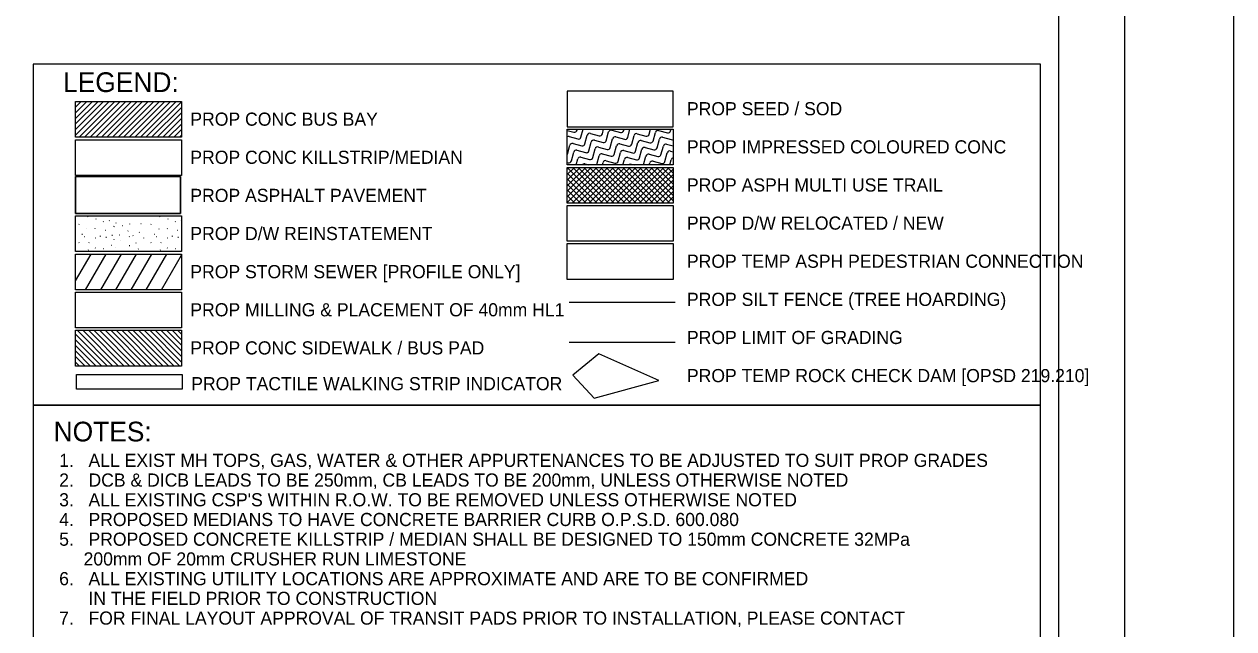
# Model space of a CAD drawing. Extents: x 595568 to 603709, y 4837996 to 4846716.
# Drawn here: x 603285 to 603377, y 4846491.1 to 4846537.1 of the extents above; entities that cross this region are included whole.
import ezdxf

# ---------------------------------------------------------------- set-up
doc = ezdxf.new("R2010")
doc.units = 0
for name, color, linetype in [('-PRINT FULLSIZE', 7, 'Continuous'), ('-PRINT HALFSIZE', 7, 'Continuous'), ('ENG_BORDER', 7, 'Continuous'), ('ENG_FENCE_SILT', 7, 'Continuous'), ('ENG_GRADING', 7, 'Continuous'), ('ENG_LEGEND', 7, 'Continuous'), ('ENG_SH_ASPHALT', 7, 'Continuous'), ('ENG_SH_CONCRETE', 7, 'Continuous'), ('ENG_SH_DRIVEWAY', 7, 'Continuous'), ('ENG_SH_GRASS', 7, 'Continuous'), ('ENG_SH_IMPRESSED', 7, 'Continuous'), ('ENG_SH_KILLSTRIP', 7, 'Continuous'), ('ENG_SH_MULTI-TRAIL', 7, 'Continuous'), ('ENG_SH_RIPRAP', 7, 'Continuous'), ('ENG_SH_STORM', 7, 'Continuous'), ('ENG_TX_LEGEND', 7, 'Continuous')]:
    doc.layers.add(name, color=color, linetype=linetype)

msp = doc.modelspace()

# ---------------------------------------------------------------- linework, layer by layer
at = {"layer": '-PRINT FULLSIZE'}
msp.add_lwpolyline([(602930.005, 4846340.645), (603377.028, 4846340.645), (603377.028, 4846645.645), (602930.005, 4846645.645)], close=True, dxfattribs=at)
at = {"layer": '-PRINT HALFSIZE'}
msp.add_lwpolyline([(602959.799, 4846631.642), (603368.716, 4846631.642), (603368.716, 4846352.642), (602959.799, 4846352.642)], close=True, dxfattribs=at)
at = {"layer": 'ENG_BORDER'}
msp.add_lwpolyline([(602975.521, 4846357.642), (603363.716, 4846357.642), (603363.716, 4846626.642), (602975.521, 4846626.642)], close=True, dxfattribs=at)
at = {"layer": 'ENG_FENCE_SILT'}
msp.add_line((603326.471, 4846515.966), (603334.527, 4846515.966), dxfattribs=at)
at = {"layer": 'ENG_GRADING'}
msp.add_line((603326.471, 4846512.922), (603334.527, 4846512.922), dxfattribs=at)
at = {"layer": 'ENG_LEGEND'}
for points in [[(603285.692, 4846508.11), (603362.309, 4846508.11), (603362.309, 4846534.05), (603285.692, 4846534.05)], [(603288.91, 4846522.699), (603296.904, 4846522.699), (603296.904, 4846525.507), (603288.91, 4846525.507)], [(603285.692, 4846471.393), (603362.309, 4846471.393), (603362.309, 4846508.11), (603285.692, 4846508.11)]]:
    msp.add_lwpolyline(points, close=True, dxfattribs=at)
at = {"layer": 'ENG_SH_ASPHALT'}
msp.add_lwpolyline([(603288.91, 4846525.507), (603296.904, 4846525.507), (603296.904, 4846522.699), (603288.91, 4846522.699)], close=True, dxfattribs=at)
at = {"layer": 'ENG_SH_CONCRETE'}
for p, q in [((603288.91, 4846531.206), (603288.92, 4846531.216)), ((603288.91, 4846530.782), (603289.344, 4846531.216)), ((603288.91, 4846530.357), (603289.768, 4846531.216)), ((603288.91, 4846529.933), (603290.193, 4846531.216)), ((603288.91, 4846529.509), (603290.617, 4846531.216)), ((603288.91, 4846529.085), (603291.041, 4846531.216)), ((603288.91, 4846528.66), (603291.465, 4846531.216)), ((603289.172, 4846528.499), (603291.89, 4846531.216)), ((603289.597, 4846528.499), (603292.314, 4846531.216)), ((603290.021, 4846528.499), (603292.738, 4846531.216)), ((603290.445, 4846528.499), (603293.162, 4846531.216)), ((603290.87, 4846528.499), (603293.587, 4846531.216)), ((603291.294, 4846528.499), (603294.011, 4846531.216)), ((603291.718, 4846528.499), (603294.435, 4846531.216)), ((603292.142, 4846528.499), (603294.86, 4846531.216)), ((603292.567, 4846528.499), (603295.284, 4846531.216)), ((603292.991, 4846528.499), (603295.708, 4846531.216)), ((603293.415, 4846528.499), (603296.132, 4846531.216)), ((603293.839, 4846528.499), (603296.557, 4846531.216)), ((603294.264, 4846528.499), (603296.965, 4846531.201)), ((603294.688, 4846528.499), (603296.965, 4846530.776)), ((603295.112, 4846528.499), (603296.965, 4846530.352)), ((603295.536, 4846528.499), (603296.965, 4846529.928)), ((603295.961, 4846528.499), (603296.965, 4846529.504)), ((603296.385, 4846528.499), (603296.965, 4846529.079)), ((603296.809, 4846528.499), (603296.965, 4846528.655)), ((603289.035, 4846513.816), (603291.752, 4846511.099)), ((603289.46, 4846513.816), (603292.177, 4846511.099)), ((603289.884, 4846513.816), (603292.601, 4846511.099)), ((603290.308, 4846513.816), (603293.025, 4846511.099)), ((603290.732, 4846513.816), (603293.45, 4846511.099)), ((603291.157, 4846513.816), (603293.874, 4846511.099)), ((603291.581, 4846513.816), (603294.298, 4846511.099)), ((603292.005, 4846513.816), (603294.722, 4846511.099)), ((603292.429, 4846513.816), (603295.147, 4846511.099)), ((603292.854, 4846513.816), (603295.571, 4846511.099)), ((603293.278, 4846513.816), (603295.995, 4846511.099)), ((603293.702, 4846513.816), (603296.419, 4846511.099)), ((603294.126, 4846513.816), (603296.844, 4846511.099)), ((603294.551, 4846513.816), (603296.965, 4846511.402)), ((603294.975, 4846513.816), (603296.965, 4846511.826)), ((603295.399, 4846513.816), (603296.965, 4846512.25)), ((603295.823, 4846513.816), (603296.965, 4846512.674)), ((603296.248, 4846513.816), (603296.965, 4846513.099)), ((603296.672, 4846513.816), (603296.965, 4846513.523)), ((603288.91, 4846513.518), (603291.328, 4846511.099)), ((603288.91, 4846513.093), (603290.904, 4846511.099)), ((603288.91, 4846512.669), (603290.48, 4846511.099)), ((603288.91, 4846512.245), (603290.055, 4846511.099)), ((603288.91, 4846511.821), (603289.631, 4846511.099)), ((603288.91, 4846511.396), (603289.207, 4846511.099))]:
    msp.add_line(p, q, dxfattribs=at)
for points in [[(603288.91, 4846531.216), (603296.965, 4846531.216), (603296.965, 4846528.499), (603288.91, 4846528.499)], [(603288.91, 4846516.716), (603296.965, 4846516.716), (603296.965, 4846513.999), (603288.91, 4846513.999)], [(603288.91, 4846513.816), (603296.965, 4846513.816), (603296.965, 4846511.099), (603288.91, 4846511.099)]]:
    msp.add_lwpolyline(points, close=True, dxfattribs=at)
at = {"layer": 'ENG_SH_DRIVEWAY'}
for p, q in [((603288.987, 4846522.516), (603289.001, 4846522.512)), ((603289.836, 4846522.467), (603289.866, 4846522.457)), ((603290.478, 4846522.266), (603290.47, 4846522.296)), ((603291.013, 4846522.082), (603291.042, 4846522.073)), ((603291.465, 4846522.151), (603291.48, 4846522.166)), ((603291.963, 4846521.996), (603291.993, 4846521.986)), ((603292.244, 4846522.502), (603292.258, 4846522.516)), ((603292.941, 4846522.502), (603292.937, 4846522.516)), ((603293.039, 4846521.894), (603293.031, 4846521.924)), ((603293.875, 4846521.952), (603293.905, 4846521.944)), ((603294.467, 4846522.516), (603294.481, 4846522.512)), ((603295.315, 4846522.467), (603295.345, 4846522.457)), ((603295.957, 4846522.266), (603295.949, 4846522.296)), ((603296.492, 4846522.082), (603296.521, 4846522.073)), ((603296.944, 4846522.151), (603296.959, 4846522.166)), ((603289.161, 4846521.864), (603289.176, 4846521.879)), ((603289.397, 4846521.134), (603289.427, 4846521.125)), ((603289.763, 4846521.522), (603289.777, 4846521.537)), ((603290.412, 4846521.528), (603290.404, 4846521.56)), ((603290.806, 4846520.958), (603290.799, 4846520.989)), ((603291.177, 4846521.443), (603291.207, 4846521.434)), ((603291.676, 4846521.06), (603291.706, 4846521.051)), ((603291.803, 4846521.733), (603291.833, 4846521.723)), ((603292.223, 4846521.086), (603292.253, 4846521.076)), ((603292.484, 4846521.789), (603292.515, 4846521.78)), ((603292.897, 4846521.363), (603292.911, 4846521.379)), ((603293.255, 4846521.02), (603293.286, 4846521.011)), ((603293.765, 4846521.253), (603293.757, 4846521.284)), ((603294.64, 4846521.864), (603294.655, 4846521.879)), ((603294.876, 4846521.134), (603294.906, 4846521.125)), ((603295.242, 4846521.522), (603295.257, 4846521.537)), ((603295.891, 4846521.528), (603295.883, 4846521.56)), ((603296.285, 4846520.958), (603296.278, 4846520.989)), ((603296.656, 4846521.443), (603296.686, 4846521.434)), ((603289.171, 4846520.458), (603289.156, 4846520.487)), ((603289.571, 4846520.943), (603289.586, 4846520.958)), ((603289.925, 4846520.478), (603289.94, 4846520.494)), ((603290.399, 4846520.08), (603290.429, 4846520.07)), ((603290.401, 4846520.846), (603290.431, 4846520.837)), ((603291.22, 4846520.901), (603291.251, 4846520.891)), ((603291.647, 4846520.289), (603291.677, 4846520.28)), ((603291.833, 4846520.694), (603291.847, 4846520.71)), ((603291.91, 4846520.078), (603291.925, 4846520.094)), ((603292.299, 4846520.612), (603292.313, 4846520.627)), ((603293.005, 4846520.919), (603292.989, 4846520.949)), ((603292.999, 4846520.274), (603293.029, 4846520.264)), ((603293.513, 4846520.453), (603293.528, 4846520.469)), ((603294.114, 4846520.825), (603294.098, 4846520.854)), ((603294.651, 4846520.458), (603294.635, 4846520.487)), ((603295.05, 4846520.943), (603295.065, 4846520.958)), ((603295.404, 4846520.478), (603295.419, 4846520.494)), ((603295.878, 4846520.08), (603295.908, 4846520.07)), ((603295.88, 4846520.846), (603295.911, 4846520.837)), ((603296.699, 4846520.901), (603296.73, 4846520.891)), ((603289.874, 4846519.915), (603289.889, 4846519.93)), ((603291.034, 4846520.042), (603291.063, 4846520.032)), ((603293.679, 4846519.996), (603293.694, 4846520.011)), ((603295.353, 4846519.915), (603295.368, 4846519.93)), ((603296.513, 4846520.042), (603296.543, 4846520.032))]:
    msp.add_line(p, q, dxfattribs=at)
for points in [[(603326.321, 4846523.309), (603334.377, 4846523.309), (603334.377, 4846520.591), (603326.321, 4846520.591)], [(603288.91, 4846522.516), (603296.965, 4846522.516), (603296.965, 4846519.799), (603288.91, 4846519.799)]]:
    msp.add_lwpolyline(points, close=True, dxfattribs=at)
at = {"layer": 'ENG_SH_GRASS'}
msp.add_lwpolyline([(603326.321, 4846529.291), (603334.377, 4846529.291), (603334.377, 4846532.009), (603326.321, 4846532.009)], close=True, dxfattribs=at)
at = {"layer": 'ENG_SH_IMPRESSED'}
for p, q in [((603326.321, 4846529.023), (603326.816, 4846528.89)), ((603326.453, 4846528.548), (603327.116, 4846528.37)), ((603327.058, 4846529.032), (603327.079, 4846529.109)), ((603327.359, 4846528.512), (603327.52, 4846529.109)), ((603327.659, 4846527.991), (603327.838, 4846528.654)), ((603328.083, 4846528.795), (603328.745, 4846528.617)), ((603328.988, 4846528.758), (603329.082, 4846529.109)), ((603329.288, 4846528.238), (603329.467, 4846528.901)), ((603329.589, 4846527.718), (603329.767, 4846528.381)), ((603329.712, 4846529.042), (603330.375, 4846528.864)), ((603330.012, 4846528.522), (603330.675, 4846528.344)), ((603330.617, 4846529.005), (603330.645, 4846529.109)), ((603330.917, 4846528.485), (603331.086, 4846529.109)), ((603331.218, 4846527.965), (603331.397, 4846528.627)), ((603331.642, 4846528.768), (603332.304, 4846528.59)), ((603332.547, 4846528.732), (603332.648, 4846529.109)), ((603332.847, 4846528.212), (603333.026, 4846528.874)), ((603333.147, 4846527.691), (603333.326, 4846528.354)), ((603333.271, 4846529.015), (603333.934, 4846528.837)), ((603333.571, 4846528.495), (603334.234, 4846528.317)), ((603334.176, 4846528.979), (603334.211, 4846529.109)), ((603326.33, 4846527.224), (603326.509, 4846527.887)), ((603326.754, 4846528.028), (603327.417, 4846527.85)), ((603327.054, 4846527.508), (603327.717, 4846527.33)), ((603327.959, 4846527.471), (603328.138, 4846528.134)), ((603328.26, 4846526.951), (603328.439, 4846527.613)), ((603328.383, 4846528.275), (603329.046, 4846528.097)), ((603328.684, 4846527.754), (603329.346, 4846527.576)), ((603329.889, 4846527.198), (603330.068, 4846527.86)), ((603330.313, 4846528.001), (603330.975, 4846527.823)), ((603330.613, 4846527.481), (603331.276, 4846527.303)), ((603331.518, 4846527.444), (603331.697, 4846528.107)), ((603331.819, 4846526.924), (603331.997, 4846527.587)), ((603331.942, 4846528.248), (603332.605, 4846528.07)), ((603332.242, 4846527.728), (603332.905, 4846527.55)), ((603333.448, 4846527.171), (603333.627, 4846527.834)), ((603333.872, 4846527.975), (603334.377, 4846527.839)), ((603334.172, 4846527.454), (603334.377, 4846527.399)), ((603326.321, 4846526.58), (603326.388, 4846526.562)), ((603326.631, 4846526.704), (603326.809, 4846527.366)), ((603326.987, 4846526.391), (603327.11, 4846526.846)), ((603327.355, 4846526.987), (603328.017, 4846526.809)), ((603328.56, 4846526.43), (603328.739, 4846527.093)), ((603328.984, 4846527.234), (603329.647, 4846527.056)), ((603328.99, 4846526.391), (603329.039, 4846526.573)), ((603329.284, 4846526.714), (603329.947, 4846526.536)), ((603330.189, 4846526.677), (603330.368, 4846527.34)), ((603330.553, 4846526.391), (603330.669, 4846526.82)), ((603330.914, 4846526.961), (603331.576, 4846526.783)), ((603332.119, 4846526.404), (603332.298, 4846527.067)), ((603332.543, 4846527.208), (603333.206, 4846527.03)), ((603332.556, 4846526.391), (603332.598, 4846526.546)), ((603332.843, 4846526.687), (603333.506, 4846526.509)), ((603333.748, 4846526.651), (603333.927, 4846527.313)), ((603334.119, 4846526.391), (603334.227, 4846526.793)), ((603327.655, 4846526.467), (603327.936, 4846526.391)), ((603331.214, 4846526.44), (603331.396, 4846526.391))]:
    msp.add_line(p, q, dxfattribs=at)
for points in [[(603326.321, 4846529.109), (603334.377, 4846529.109), (603334.377, 4846526.391), (603326.321, 4846526.391)], [(603288.975, 4846510.453), (603297.031, 4846510.453), (603297.031, 4846509.327), (603288.975, 4846509.327)]]:
    msp.add_lwpolyline(points, close=True, dxfattribs=at)
for centre, start, end in [((603326.402, 4846528.355), 74.96607, 113.68387), ((603326.868, 4846529.086), 255.09778, 299.63469), ((603326.865, 4846529.084), 300.36526, 344.90216), ((603327.168, 4846528.565), 255.09778, 299.63469), ((603327.165, 4846528.564), 300.36526, 344.90216), ((603328.031, 4846528.602), 74.96607, 164.90216), ((603328.797, 4846528.812), 255.09778, 299.63469), ((603328.795, 4846528.811), 300.36526, 344.90216), ((603329.66, 4846528.849), 74.96607, 164.90216), ((603329.96, 4846528.328), 74.96607, 164.90216), ((603330.427, 4846529.059), 255.09778, 299.63469), ((603330.424, 4846529.057), 300.36526, 344.90216), ((603330.727, 4846528.539), 255.09778, 299.63469), ((603330.724, 4846528.537), 300.36526, 344.90216), ((603331.59, 4846528.575), 74.96607, 164.90216), ((603332.056, 4846529.306), 260.67769, 279.32225), ((603332.356, 4846528.786), 255.09778, 299.63469), ((603332.353, 4846528.784), 300.36526, 344.90216), ((603333.219, 4846528.822), 74.96607, 164.90216), ((603333.519, 4846528.302), 74.96607, 164.90216), ((603333.986, 4846529.033), 255.09778, 299.63469), ((603333.983, 4846529.031), 300.36526, 344.90216), ((603326.702, 4846527.835), 74.96607, 164.90216), ((603327.002, 4846527.314), 74.96607, 164.90216), ((603327.469, 4846528.045), 255.09778, 299.63469), ((603327.466, 4846528.043), 300.36526, 344.90216), ((603327.766, 4846527.523), 300.36526, 344.90216), ((603328.331, 4846528.082), 74.96607, 164.90216), ((603328.632, 4846527.561), 74.96607, 164.90216), ((603329.098, 4846528.292), 255.09778, 299.63469), ((603329.095, 4846528.29), 300.36526, 344.90216), ((603329.398, 4846527.772), 255.09778, 299.63469), ((603329.395, 4846527.77), 300.36526, 344.90216), ((603330.261, 4846527.808), 74.96607, 164.90216), ((603330.561, 4846527.288), 74.96607, 164.90216), ((603331.027, 4846528.019), 255.09778, 299.63469), ((603331.025, 4846528.017), 300.36526, 344.90216), ((603331.325, 4846527.497), 300.36526, 344.90216), ((603331.89, 4846528.055), 74.96607, 164.90216), ((603332.19, 4846527.535), 74.96607, 164.90216), ((603332.657, 4846528.265), 255.09778, 299.63469), ((603332.654, 4846528.264), 300.36526, 344.90216), ((603332.957, 4846527.745), 255.09778, 299.63469), ((603332.954, 4846527.743), 300.36526, 344.90216), ((603333.82, 4846527.782), 74.96607, 164.90216), ((603334.12, 4846527.261), 74.96607, 164.90216), ((603334.286, 4846528.512), 255.09778, 297.11531), ((603326.137, 4846527.276), 337.19287, 344.90216), ((603326.44, 4846526.758), 255.09778, 299.63469), ((603326.437, 4846526.756), 300.36526, 344.90216), ((603327.303, 4846526.794), 74.96607, 164.90216), ((603327.769, 4846527.525), 255.09778, 299.63469), ((603328.069, 4846527.004), 255.09778, 299.63469), ((603328.067, 4846527.003), 300.36526, 344.90216), ((603328.932, 4846527.041), 74.96607, 164.90216), ((603329.232, 4846526.521), 74.96607, 164.90216), ((603329.699, 4846527.251), 255.09778, 299.63469), ((603329.696, 4846527.25), 300.36526, 344.90216), ((603329.999, 4846526.731), 255.09778, 299.63469), ((603329.996, 4846526.729), 300.36526, 344.90216), ((603330.862, 4846526.768), 74.96607, 164.90216), ((603331.328, 4846527.498), 255.09778, 299.63469), ((603331.628, 4846526.978), 255.09778, 299.63469), ((603331.625, 4846526.976), 300.36526, 344.90216), ((603332.491, 4846527.014), 74.96607, 164.90216), ((603332.791, 4846526.494), 74.96607, 164.90216), ((603333.257, 4846527.225), 255.09778, 299.63469), ((603333.255, 4846527.223), 300.36526, 344.90216), ((603333.558, 4846526.704), 255.09778, 299.63469), ((603333.555, 4846526.703), 300.36526, 344.90216), ((603334.421, 4846526.741), 102.5484, 164.90216), ((603327.603, 4846526.274), 74.96607, 143.93922), ((603328.367, 4846526.482), 332.93177, 344.90216), ((603331.162, 4846526.247), 74.96607, 133.84106), ((603331.926, 4846526.456), 341.19003, 344.90216)]:
    msp.add_arc(centre, 0.2, start, end, dxfattribs=at)
at = {"layer": 'ENG_SH_KILLSTRIP'}
msp.add_lwpolyline([(603288.91, 4846528.316), (603296.965, 4846528.316), (603296.965, 4846525.599), (603288.91, 4846525.599)], close=True, dxfattribs=at)
at = {"layer": 'ENG_SH_MULTI-TRAIL'}
for p, q in [((603326.321, 4846526.085), (603326.445, 4846526.209)), ((603326.321, 4846525.661), (603326.869, 4846526.209)), ((603326.321, 4846525.236), (603327.293, 4846526.209)), ((603326.321, 4846524.812), (603327.718, 4846526.209)), ((603326.321, 4846524.388), (603328.142, 4846526.209)), ((603326.321, 4846523.964), (603328.566, 4846526.209)), ((603326.321, 4846523.539), (603328.991, 4846526.209)), ((603326.321, 4846526.197), (603329.027, 4846523.491)), ((603326.321, 4846525.773), (603328.602, 4846523.491)), ((603326.698, 4846523.491), (603329.415, 4846526.209)), ((603326.734, 4846526.209), (603329.451, 4846523.491)), ((603327.122, 4846523.491), (603329.839, 4846526.209)), ((603327.158, 4846526.209), (603329.875, 4846523.491)), ((603327.546, 4846523.491), (603330.263, 4846526.209)), ((603327.582, 4846526.209), (603330.299, 4846523.491)), ((603327.97, 4846523.491), (603330.688, 4846526.209)), ((603328.007, 4846526.209), (603330.724, 4846523.491)), ((603328.395, 4846523.491), (603331.112, 4846526.209)), ((603328.431, 4846526.209), (603331.148, 4846523.491)), ((603328.819, 4846523.491), (603331.536, 4846526.209)), ((603328.855, 4846526.209), (603331.572, 4846523.491)), ((603329.243, 4846523.491), (603331.96, 4846526.209)), ((603329.279, 4846526.209), (603331.997, 4846523.491)), ((603329.667, 4846523.491), (603332.385, 4846526.209)), ((603329.704, 4846526.209), (603332.421, 4846523.491)), ((603330.092, 4846523.491), (603332.809, 4846526.209)), ((603330.128, 4846526.209), (603332.845, 4846523.491)), ((603330.516, 4846523.491), (603333.233, 4846526.209)), ((603330.552, 4846526.209), (603333.269, 4846523.491)), ((603330.94, 4846523.491), (603333.657, 4846526.209)), ((603330.976, 4846526.209), (603333.694, 4846523.491)), ((603331.364, 4846523.491), (603334.082, 4846526.209)), ((603331.401, 4846526.209), (603334.118, 4846523.491)), ((603331.789, 4846523.491), (603334.377, 4846526.08)), ((603331.825, 4846526.209), (603334.377, 4846523.657)), ((603332.213, 4846523.491), (603334.377, 4846525.656)), ((603332.249, 4846526.209), (603334.377, 4846524.081)), ((603332.673, 4846526.209), (603334.377, 4846524.505)), ((603333.098, 4846526.209), (603334.377, 4846524.929)), ((603333.522, 4846526.209), (603334.377, 4846525.354)), ((603333.946, 4846526.209), (603334.377, 4846525.778)), ((603334.37, 4846526.209), (603334.377, 4846526.202)), ((603326.321, 4846525.348), (603328.178, 4846523.491)), ((603326.321, 4846524.924), (603327.754, 4846523.491)), ((603332.637, 4846523.491), (603334.377, 4846525.231)), ((603333.062, 4846523.491), (603334.377, 4846524.807)), ((603326.321, 4846524.5), (603327.33, 4846523.491)), ((603326.321, 4846524.076), (603326.905, 4846523.491)), ((603333.486, 4846523.491), (603334.377, 4846524.383)), ((603333.91, 4846523.491), (603334.377, 4846523.958))]:
    msp.add_line(p, q, dxfattribs=at)
for points in [[(603326.321, 4846526.209), (603334.377, 4846526.209), (603334.377, 4846523.491), (603326.321, 4846523.491)], [(603326.321, 4846520.409), (603334.377, 4846520.409), (603334.377, 4846517.691), (603326.321, 4846517.691)]]:
    msp.add_lwpolyline(points, close=True, dxfattribs=at)
at = {"layer": 'ENG_SH_RIPRAP'}
msp.add_lwpolyline([(603328.713, 4846512.019), (603326.753, 4846510.397), (603328.375, 4846508.65), (603333.289, 4846509.999)], close=True, dxfattribs=at)
at = {"layer": 'ENG_SH_STORM'}
for p, q in [((603288.91, 4846519.58), (603288.931, 4846519.616)), ((603288.91, 4846517.58), (603290.085, 4846519.616)), ((603289.671, 4846516.899), (603291.24, 4846519.616)), ((603290.826, 4846516.899), (603292.395, 4846519.616)), ((603291.981, 4846516.899), (603293.549, 4846519.616)), ((603293.135, 4846516.899), (603294.704, 4846519.616)), ((603294.29, 4846516.899), (603295.859, 4846519.616)), ((603295.445, 4846516.899), (603296.965, 4846519.533))]:
    msp.add_line(p, q, dxfattribs=at)
msp.add_lwpolyline([(603288.91, 4846519.616), (603296.965, 4846519.616), (603296.965, 4846516.899), (603288.91, 4846516.899)], close=True, dxfattribs=at)

# ---------------------------------------------------------------- texts
at = {"layer": 'ENG_TX_LEGEND'}
for s, height, rotation, p in [('LEGEND:', 1.5, 359.99997, (603287.955, 4846531.94)), ('PROP SEED / SOD', 1, 359.99997, (603335.422, 4846530.17)), ('PROP CONC BUS BAY', 1, 359.99997, (603297.641, 4846529.377)), ('PROP CONC KILLSTRIP/MEDIAN', 1, 359.99997, (603297.641, 4846526.477)), ('PROP IMPRESSED COLOURED CONC', 1, 359.99997, (603335.422, 4846527.27)), ('PROP ASPH MULTI USE TRAIL', 1, 359.99997, (603335.422, 4846524.37)), ('PROP ASPHALT PAVEMENT', 1, 359.99997, (603297.641, 4846523.577)), ('PROP D/W RELOCATED / NEW', 1, 359.99997, (603335.422, 4846521.47)), ('PROP D/W REINSTATEMENT', 1, 359.99997, (603297.641, 4846520.677)), ('PROP TEMP ASPH PEDESTRIAN CONNECTION', 1, 359.99997, (603335.422, 4846518.57)), ('PROP STORM SEWER [PROFILE ONLY]', 1, 359.99997, (603297.641, 4846517.777)), ('PROP SILT FENCE (TREE HOARDING)', 1, 359.99997, (603335.422, 4846515.67)), ('PROP MILLING & PLACEMENT OF 40mm HL1', 1, 359.99997, (603297.641, 4846514.877)), ('PROP LIMIT OF GRADING', 1, 359.99997, (603335.422, 4846512.77)), ('PROP CONC SIDEWALK / BUS PAD', 1, 359.99997, (603297.641, 4846511.977)), ('PROP TEMP ROCK CHECK DAM [OPSD 219.210]', 1, 359.99997, (603335.422, 4846509.87)), ('PROP TACTILE WALKING STRIP INDICATOR', 1, 359.99994, (603297.706, 4846509.256)), ('NOTES:', 1.5, 359.99997, (603287.237, 4846505.361)), (' 1.   ALL EXIST MH TOPS, GAS, WATER & OTHER APPURTENANCES TO BE ADJUSTED TO SUIT PROP GRADES', 1, 359.99997, (603287.29, 4846503.424)), (' 2.   DCB & DICB LEADS TO BE 250mm, CB LEADS TO BE 200mm, UNLESS OTHERWISE NOTED', 1, 359.99997, (603287.29, 4846501.924)), (" 3.   ALL EXISTING CSP'S WITHIN R.O.W. TO BE REMOVED UNLESS OTHERWISE NOTED", 1, 359.99997, (603287.29, 4846500.424)), (' 4.   PROPOSED MEDIANS TO HAVE CONCRETE BARRIER CURB O.P.S.D. 600.080', 1, 359.99997, (603287.29, 4846498.924)), (' 5.   PROPOSED CONCRETE KILLSTRIP / MEDIAN SHALL BE DESIGNED TO 150mm CONCRETE 32MPa', 1, 359.99997, (603287.29, 4846497.424)), ('      200mm OF 20mm CRUSHER RUN LIMESTONE', 1, 359.99997, (603287.29, 4846495.924)), (' 6.   ALL EXISTING UTILITY LOCATIONS ARE APPROXIMATE AND ARE TO BE CONFIRMED', 1, 359.99997, (603287.29, 4846494.424)), ('       IN THE FIELD PRIOR TO CONSTRUCTION', 1, 359.99997, (603287.29, 4846492.924)), (' 7.   FOR FINAL LAYOUT APPROVAL OF TRANSIT PADS PRIOR TO INSTALLATION, PLEASE CONTACT', 1, 359.99997, (603287.29, 4846491.424))]:
    msp.add_text(s, height=height, rotation=rotation, dxfattribs=at).set_placement(p)

doc.saveas('drawing.dxf')
